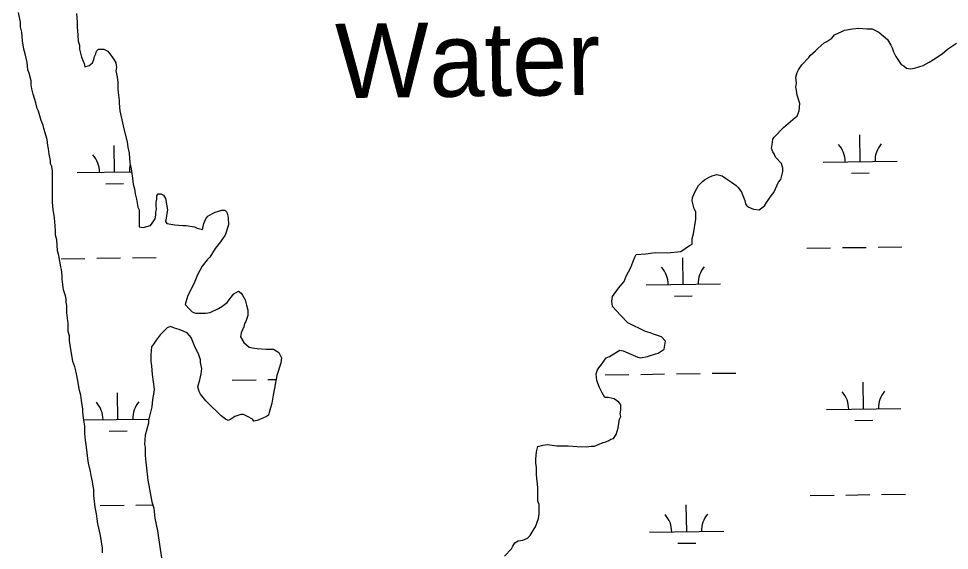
# Model space of a CAD drawing. Extents: x 3775218 to 3813389, y 343470 to 369318.
# Drawn here: x 3787496 to 3788749, y 357893 to 358608 of the extents above; entities that cross this region are included whole.
import ezdxf

# ---------------------------------------------------------------- set-up
doc = ezdxf.new("R2010")
doc.units = 0
for name, color, linetype in [('V-RIVR-IDEN', 7, 'Continuous'), ('V-TOPO-SHOR', 7, 'Continuous'), ('V-WETL-SWMP', 7, 'Continuous')]:
    doc.layers.add(name, color=color, linetype=linetype)

msp = doc.modelspace()

# ---------------------------------------------------------------- linework, layer by layer
at = {"layer": 'V-TOPO-SHOR'}
for points in [[(3787584.7, 358049.9), (3787584.7, 358059.9), (3787582.9, 358070.8), (3787582.1, 358079), (3787582.1, 358082.6), (3787580.3, 358094.4), (3787579.4, 358101.7), (3787577.6, 358108), (3787574.9, 358123.4), (3787573.2, 358132.5), (3787571.4, 358139.8), (3787568.7, 358147), (3787565.1, 358168.8), (3787564.2, 358175.2), (3787564.2, 358181.5), (3787562.4, 358187), (3787562.5, 358197.9), (3787560.7, 358212.4), (3787560.7, 358222.4), (3787559.8, 358226.9), (3787559.9, 358230.5), (3787559, 358235.1), (3787556.3, 358243.2), (3787554.5, 358257.7), (3787554.5, 358262.3), (3787553.6, 358270.4), (3787552.7, 358274.1), (3787550.1, 358289.5), (3787548.3, 358295.9), (3787547.4, 358310.4), (3787545.6, 358316.7), (3787545.6, 358322.2), (3787544.8, 358329.4), (3787543.9, 358340.3), (3787542.1, 358351.2), (3787541.2, 358361.2), (3787541.4, 358402.9), (3787540.5, 358409.3), (3787538.7, 358412.9), (3787538.7, 358417.4), (3787536.9, 358425.6), (3787536, 358432.9), (3787535.1, 358437.4), (3787534.2, 358445.6), (3787529.7, 358460.1), (3787528.9, 358464.6), (3787526.2, 358471), (3787522.6, 358483.7), (3787520.8, 358487.3), (3787519, 358494.6), (3787515.4, 358506.4), (3787513.6, 358513.6), (3787512.7, 358519.1), (3787512.7, 358524.5), (3787510, 358534.5), (3787508.2, 358539.1), (3787507.4, 358549), (3787504.7, 358560.8), (3787502.9, 358567.2), (3787501.1, 358578.1), (3787500.2, 358589.9), (3787498.4, 358597.1), (3787498.5, 358603.5), (3787495.8, 358616.2)], [(3787573.5, 358615), (3787574.4, 358603.2), (3787574.4, 358596.9), (3787575.3, 358586), (3787576.1, 358577.8), (3787577.9, 358572.4), (3787577.9, 358566.9), (3787580.6, 358556), (3787584.2, 358547.9), (3787585.1, 358543.3), (3787590.6, 358545.1), (3787595.1, 358548.7), (3787596.9, 358553.3), (3787597.8, 358556.9), (3787599.7, 358560.5), (3787600.6, 358564.1), (3787603.3, 358566.8), (3787610.6, 358566.8), (3787616, 358564.1), (3787622.3, 358555.9), (3787624.1, 358553.2), (3787626.8, 358548.6), (3787627.7, 358542.3), (3787626.8, 358537.7), (3787628.6, 358529.6), (3787629.5, 358522.3), (3787629.5, 358512.3), (3787631.2, 358497.8), (3787631.2, 358494.2), (3787632.1, 358484.2), (3787637.4, 358459.7), (3787641.9, 358442.5), (3787642.8, 358435.2), (3787644.6, 358427), (3787645.5, 358414.3), (3787647.3, 358406.2), (3787649, 358393.5)], [(3788352.5, 358293.3), (3788368.9, 358293.2), (3788387, 358295), (3788398.8, 358303.1), (3788402.5, 358304.9), (3788402.5, 358312.2), (3788404.3, 358318.5), (3788407.1, 358338.4), (3788407.1, 358348.4), (3788405.3, 358352.1), (3788402.6, 358362.9), (3788402.7, 358367.5), (3788406.3, 358375.6), (3788410.9, 358383.8), (3788416.3, 358389.2), (3788419.1, 358391), (3788425.4, 358394.6), (3788429.1, 358396.4), (3788435.4, 358398.2), (3788442.7, 358396.4), (3788447.2, 358393.6), (3788455.3, 358388.2), (3788461.7, 358383.6), (3788464.4, 358380.9), (3788468.9, 358374.5), (3788473.4, 358363.6), (3788474.3, 358359.1), (3788476.1, 358356.4), (3788478.8, 358354.5), (3788485.1, 358351.8), (3788492.4, 358350.9), (3788499.7, 358356.3), (3788502.4, 358360.8), (3788508.8, 358369.9), (3788512.4, 358374.4), (3788518.8, 358388), (3788521.6, 358391.6), (3788524.3, 358402.5), (3788524.3, 358407), (3788522.5, 358413.4), (3788514.4, 358421.5), (3788512.6, 358426.1), (3788510.8, 358428.8), (3788509, 358433.4), (3788509.9, 358438.8), (3788510.8, 358446), (3788512.7, 358448.8), (3788525.4, 358461.4), (3788540.9, 358475), (3788543.6, 358476.8), (3788546.3, 358484), (3788547.3, 358494), (3788543.7, 358504.9), (3788542.8, 358511.3), (3788541.9, 358515.8), (3788542.8, 358521.2), (3788541.9, 358529.4), (3788543.8, 358535.7), (3788545.6, 358539.4), (3788550.2, 358545.7), (3788559.3, 358555.6), (3788561.1, 358558.4), (3788568.4, 358564.7), (3788572, 358568.3), (3788580.2, 358575.5), (3788583.8, 358577.3), (3788590.2, 358581.8), (3788593.8, 358586.4), (3788603.8, 358590.9), (3788607.4, 358592.7), (3788618.3, 358594.5), (3788626.5, 358595.3), (3788637.4, 358594.4), (3788644.6, 358594.4), (3788653.7, 358589.8), (3788665.5, 358579.8), (3788670, 358572.5), (3788671.8, 358568.9), (3788673.6, 358563.4), (3788676.3, 358557.1), (3788683.5, 358546.2), (3788687.1, 358544.4), (3788690.7, 358541.6), (3788696.2, 358540.7), (3788701.6, 358541.6), (3788713.4, 358545.2), (3788721.6, 358549.7), (3788727, 358553.3), (3788738.9, 358560.5), (3788746.1, 358566.8), (3788758, 358575)], [(3787649, 358393.5), (3787649.9, 358385.3), (3787651.7, 358378.9), (3787652.6, 358372.6), (3787654.4, 358365.3), (3787656.2, 358354.4), (3787658, 358350.8), (3787657.9, 358328.1), (3787663.3, 358327.2), (3787673.3, 358329.9), (3787677.9, 358336.2), (3787679.7, 358338.9), (3787680.6, 358343.5), (3787680.6, 358348), (3787681.5, 358351.6), (3787680.7, 358356.2), (3787680.7, 358360.7), (3787681.6, 358365.2), (3787681.6, 358369.8), (3787683.4, 358372.5), (3787687.1, 358372.5), (3787690.7, 358370.6), (3787693.4, 358366.1), (3787696.1, 358350.7), (3787695.1, 358346.1), (3787694.2, 358339.8), (3787693.3, 358335.3), (3787695.1, 358332.5), (3787706, 358330.7), (3787716.9, 358329.8), (3787721.4, 358329.7), (3787732.3, 358327.9), (3787735.9, 358326.1), (3787743.1, 358324.2), (3787745, 358332.4), (3787747.7, 358338.7), (3787750.5, 358342.3), (3787756.8, 358345.9), (3787760.4, 358347.8), (3787769.5, 358350.4), (3787773.2, 358350.4), (3787775.9, 358347.7), (3787777.7, 358340.4), (3787778.5, 358330.5), (3787774, 358316.9), (3787771.2, 358313.3), (3787767.6, 358307.8), (3787760.3, 358298.8), (3787753, 358287), (3787749.4, 358283.4), (3787743, 358275.2), (3787736.6, 358263.5), (3787732.9, 358254.4), (3787722.9, 358234.5), (3787720.1, 358223.6), (3787725.6, 358217.3), (3787729.2, 358213.6), (3787733.7, 358211.8), (3787747.3, 358211.7), (3787753.7, 358212.6), (3787764.6, 358218), (3787769.1, 358220.7), (3787776.4, 358226.2), (3787781.9, 358233.4), (3787785.5, 358237.9), (3787791.9, 358241.5), (3787795.5, 358238.8), (3787797.3, 358236.1), (3787800.9, 358229.7), (3787802.7, 358222.5), (3787804.5, 358216.1), (3787804.4, 358208.8), (3787801.7, 358200.7), (3787799.9, 358198), (3787799, 358193.4), (3787795.3, 358185.3), (3787794.4, 358179.9), (3787798.9, 358172.6), (3787806.1, 358166.2), (3787810.7, 358165.3), (3787817, 358164.4), (3787828.8, 358163.4), (3787838.8, 358163.4), (3787846, 358158.8), (3787849.6, 358151.6), (3787848.7, 358145.2), (3787845, 358133.4), (3787843.2, 358128), (3787840.4, 358110.8), (3787838.6, 358101.7), (3787836.7, 358090.8), (3787833.1, 358078.1), (3787832.1, 358074.5), (3787829.4, 358072.7), (3787821.2, 358069.1), (3787816.7, 358067.3), (3787812.2, 358066.4), (3787810.4, 358069.1), (3787804, 358072.8), (3787798.6, 358075.5), (3787795, 358075.5)], [(3788149.9, 357884.9), (3788159, 357894.8), (3788160.8, 357898.4), (3788163.6, 357903), (3788168.1, 357905.7), (3788174.5, 357906.5), (3788180.8, 357909.2), (3788184.4, 357912.9), (3788189.9, 357921.9), (3788191.7, 357924.6), (3788195.4, 357935.5), (3788196.3, 357941.8), (3788196.4, 357954.5), (3788194.6, 357959.1), (3788194.6, 357977.2), (3788192.9, 357994.5), (3788192.9, 358004.4), (3788192, 358009.9), (3788192, 358015.3), (3788193, 358025.3), (3788194.8, 358032.6), (3788201.2, 358034.3), (3788207.5, 358035.2), (3788220.2, 358033.4), (3788235.6, 358033.3), (3788247.4, 358032.4), (3788260.1, 358032.3), (3788266.5, 358033.2), (3788271, 358033.2), (3788277.4, 358035.9), (3788282.8, 358037.7), (3788286.4, 358038.6), (3788290.1, 358040.4), (3788292.8, 358042.2), (3788296.4, 358043.1), (3788300.1, 358048.5), (3788302.8, 358057.6), (3788304.7, 358069.4), (3788306.5, 358073), (3788305.6, 358076.6), (3788306.5, 358081.2), (3788306.5, 358088.4), (3788303.8, 358092.1), (3788297.5, 358096.6), (3788289.3, 358098.5), (3788284.8, 358098.5), (3788281.2, 358104.8), (3788277.6, 358112.1), (3788274, 358121.2), (3788273.1, 358130.3), (3788274.9, 358135.7), (3788276.8, 358138.4), (3788280.4, 358142.9), (3788286.8, 358152), (3788291.3, 358153.8), (3788305, 358161.9), (3788309.5, 358161), (3788329.4, 358152.8), (3788333, 358151.8), (3788342.1, 358153.6), (3788353, 358157.2), (3788356.6, 358158.1), (3788364.8, 358163.5), (3788366.7, 358174.4), (3788361.3, 358179.9), (3788350.4, 358183.5), (3788345.9, 358185.4), (3788339.5, 358187.2), (3788316, 358199.1), (3788306, 358209.1), (3788295.2, 358220.9), (3788294.3, 358228.2), (3788295.2, 358234.5), (3788303.4, 358245.4), (3788310.7, 358254.4), (3788313.4, 358261.6), (3788319.8, 358273.4), (3788322.6, 358280.7), (3788325.3, 358287), (3788327.1, 358290.6), (3788339.8, 358291.5), (3788352.5, 358293.3)], [(3787795, 358075.5), (3787786.8, 358072.8), (3787781.3, 358069.2), (3787777.7, 358067.4), (3787774.1, 358069.3), (3787768.6, 358073.8), (3787764.1, 358078.4), (3787754.2, 358087.5), (3787747.8, 358093.8), (3787740.6, 358102.9), (3787738.8, 358106.6), (3787737, 358112.9), (3787739.8, 358122), (3787741.6, 358130.1), (3787742.5, 358137.4), (3787740.8, 358145.6), (3787740.8, 358149.2), (3787738.1, 358157.4), (3787733.6, 358165.5), (3787728.2, 358179.2), (3787722.7, 358185.5), (3787711.9, 358190.1), (3787705.5, 358191.9), (3787700.1, 358193.8), (3787695.6, 358192), (3787686.5, 358182.9), (3787681, 358175.7), (3787677.3, 358170.2), (3787674.6, 358166.6), (3787673.7, 358155.7), (3787673.6, 358146.7), (3787674.5, 358141.2), (3787675.4, 358129.4), (3787678.1, 358109.5), (3787678, 358105.8), (3787676.2, 358095.9), (3787675.3, 358085.9), (3787670.7, 358067.8), (3787670.7, 358064.1), (3787666.1, 358047.8), (3787665.1, 358035.1), (3787666, 358031.5), (3787666, 358020.6), (3787666.9, 358011.6), (3787669.5, 357987.1), (3787674.9, 357958), (3787677.6, 357949.8), (3787679.3, 357936.2), (3787682.9, 357919), (3787686.4, 357894.5), (3787690, 357871.8)], [(3787608.7, 357889.3), (3787608.7, 357895.7), (3787606, 357912.9), (3787602.4, 357928.4), (3787600.7, 357942), (3787598.9, 357951), (3787597.1, 357966.5), (3787597.1, 357974.6), (3787596.2, 357979.2), (3787595.4, 357985.5), (3787593.6, 357993.7), (3787592.7, 357999.1), (3787590, 358010), (3787589.1, 358016.4), (3787587.3, 358031.8), (3787585.6, 358040.9), (3787584.7, 358049.9)]]:
    msp.add_lwpolyline(points, dxfattribs=at)
at = {"layer": 'V-WETL-SWMP'}
for p, q in [((3788628.5, 358415.8), (3788627.9, 358451.7)), ((3787624.7, 358401.6), (3787624.2, 358437.6)), ((3788578.5, 358415), (3788678.5, 358416.5)), ((3787574.7, 358400.9), (3787647.8, 358401.9)), ((3788616.7, 358400.2), (3788640.7, 358400.5)), ((3787613, 358386), (3787637, 358386.3)), ((3788556.7, 358299.3), (3788588.7, 358299.7)), ((3788604.7, 358300), (3788636.7, 358300.4)), ((3788652.7, 358300.6), (3788684.7, 358301.1)), ((3787553, 358285.1), (3787585, 358285.6)), ((3787601, 358285.8), (3787633, 358286.3)), ((3787649, 358286.5), (3787681, 358286.9)), ((3788390.3, 358250.5), (3788389.8, 358286.5)), ((3788340.3, 358249.8), (3788440.3, 358251.2)), ((3788378.5, 358234.9), (3788402.5, 358235.3)), ((3787783.3, 358121.9), (3787815.3, 358122.3)), ((3787831.3, 358122.5), (3787842.3, 358122.7)), ((3788285.2, 358128.9), (3788317.2, 358129.4)), ((3788333.1, 358129.6), (3788365.1, 358130.1)), ((3788381.1, 358130.3), (3788413.1, 358130.8)), ((3788429.1, 358131), (3788461.1, 358131.4)), ((3788633.2, 358083.1), (3788632.6, 358119.1)), ((3787629.4, 358068.9), (3787628.9, 358104.9)), ((3788583.2, 358082.4), (3788683.1, 358083.8)), ((3787583.3, 358068.3), (3787671.1, 358069.5)), ((3788621.4, 358067.5), (3788645.4, 358067.8)), ((3787617.7, 358053.3), (3787641.7, 358053.7)), ((3788561.4, 357966.7), (3788593.4, 357967.1)), ((3788609.4, 357967.3), (3788641.4, 357967.8)), ((3788657.4, 357968), (3788689.4, 357968.5)), ((3787605.7, 357953.2), (3787637.7, 357953.6)), ((3787653.7, 357953.8), (3787676.1, 357954.2)), ((3788395, 357917.9), (3788394.5, 357953.9)), ((3788345, 357917.2), (3788445, 357918.6)), ((3788383.2, 357902.3), (3788407.2, 357902.6))]:
    msp.add_line(p, q, dxfattribs=at)
for points in [[(3787584.7, 358049.9), (3787584.7, 358059.9), (3787582.9, 358070.8), (3787582.1, 358079), (3787582.1, 358082.6), (3787580.3, 358094.4), (3787579.4, 358101.7), (3787577.6, 358108), (3787574.9, 358123.4), (3787573.2, 358132.5), (3787571.4, 358139.8), (3787568.7, 358147), (3787565.1, 358168.8), (3787564.2, 358175.2), (3787564.2, 358181.5), (3787562.4, 358187), (3787562.5, 358197.9), (3787560.7, 358212.4), (3787560.7, 358222.4), (3787559.8, 358226.9), (3787559.9, 358230.5), (3787559, 358235.1), (3787556.3, 358243.2), (3787554.5, 358257.7), (3787554.5, 358262.3), (3787553.6, 358270.4), (3787552.7, 358274.1), (3787550.1, 358289.5), (3787548.3, 358295.9), (3787547.4, 358310.4), (3787545.6, 358316.7), (3787545.6, 358322.2), (3787544.8, 358329.4), (3787543.9, 358340.3), (3787542.1, 358351.2), (3787541.2, 358361.2), (3787541.4, 358402.9), (3787540.5, 358409.3), (3787538.7, 358412.9), (3787538.7, 358417.4), (3787536.9, 358425.6), (3787536, 358432.9), (3787535.1, 358437.4), (3787534.2, 358445.6), (3787529.7, 358460.1), (3787528.9, 358464.6), (3787526.2, 358471), (3787522.6, 358483.7), (3787520.8, 358487.3), (3787519, 358494.6), (3787515.4, 358506.4), (3787513.6, 358513.6), (3787512.7, 358519.1), (3787512.7, 358524.5), (3787510, 358534.5), (3787508.2, 358539.1), (3787507.4, 358549), (3787504.7, 358560.8), (3787502.9, 358567.2), (3787501.1, 358578.1), (3787500.2, 358589.9), (3787498.4, 358597.1), (3787498.5, 358603.5), (3787495.8, 358616.2)], [(3787573.5, 358615), (3787574.4, 358603.2), (3787574.4, 358596.9), (3787575.3, 358586), (3787576.1, 358577.8), (3787577.9, 358572.4), (3787577.9, 358566.9), (3787580.6, 358556), (3787584.2, 358547.9), (3787585.1, 358543.3), (3787590.6, 358545.1), (3787595.1, 358548.7), (3787596.9, 358553.3), (3787597.8, 358556.9), (3787599.7, 358560.5), (3787600.6, 358564.1), (3787603.3, 358566.8), (3787610.6, 358566.8), (3787616, 358564.1), (3787622.3, 358555.9), (3787624.1, 358553.2), (3787626.8, 358548.6), (3787627.7, 358542.3), (3787626.8, 358537.7), (3787628.6, 358529.6), (3787629.5, 358522.3), (3787629.5, 358512.3), (3787631.2, 358497.8), (3787631.2, 358494.2), (3787632.1, 358484.2), (3787637.4, 358459.7), (3787641.9, 358442.5), (3787642.8, 358435.2), (3787644.6, 358427), (3787645.5, 358414.3), (3787647.3, 358406.2), (3787649, 358393.5)], [(3788352.5, 358293.3), (3788368.9, 358293.2), (3788387, 358295), (3788398.8, 358303.1), (3788402.5, 358304.9), (3788402.5, 358312.2), (3788404.3, 358318.5), (3788407.1, 358338.4), (3788407.1, 358348.4), (3788405.3, 358352.1), (3788402.6, 358362.9), (3788402.7, 358367.5), (3788406.3, 358375.6), (3788410.9, 358383.8), (3788416.3, 358389.2), (3788419.1, 358391), (3788425.4, 358394.6), (3788429.1, 358396.4), (3788435.4, 358398.2), (3788442.7, 358396.4), (3788447.2, 358393.6), (3788455.3, 358388.2), (3788461.7, 358383.6), (3788464.4, 358380.9), (3788468.9, 358374.5), (3788473.4, 358363.6), (3788474.3, 358359.1), (3788476.1, 358356.4), (3788478.8, 358354.5), (3788485.1, 358351.8), (3788492.4, 358350.9), (3788499.7, 358356.3), (3788502.4, 358360.8), (3788508.8, 358369.9), (3788512.4, 358374.4), (3788518.8, 358388), (3788521.6, 358391.6), (3788524.3, 358402.5), (3788524.3, 358407), (3788522.5, 358413.4), (3788514.4, 358421.5), (3788512.6, 358426.1), (3788510.8, 358428.8), (3788509, 358433.4), (3788509.9, 358438.8), (3788510.8, 358446), (3788512.7, 358448.8), (3788525.4, 358461.4), (3788540.9, 358475), (3788543.6, 358476.8), (3788546.3, 358484), (3788547.3, 358494), (3788543.7, 358504.9), (3788542.8, 358511.3), (3788541.9, 358515.8), (3788542.8, 358521.2), (3788541.9, 358529.4), (3788543.8, 358535.7), (3788545.6, 358539.4), (3788550.2, 358545.7), (3788559.3, 358555.6), (3788561.1, 358558.4), (3788568.4, 358564.7), (3788572, 358568.3), (3788580.2, 358575.5), (3788583.8, 358577.3), (3788590.2, 358581.8), (3788593.8, 358586.4), (3788603.8, 358590.9), (3788607.4, 358592.7), (3788618.3, 358594.5), (3788626.5, 358595.3), (3788637.4, 358594.4), (3788644.6, 358594.4), (3788653.7, 358589.8), (3788665.5, 358579.8), (3788670, 358572.5), (3788671.8, 358568.9), (3788673.6, 358563.4), (3788676.3, 358557.1), (3788683.5, 358546.2), (3788687.1, 358544.4), (3788690.7, 358541.6), (3788696.2, 358540.7), (3788701.6, 358541.6), (3788713.4, 358545.2), (3788721.6, 358549.7), (3788727, 358553.3), (3788738.9, 358560.5), (3788746.1, 358566.8), (3788758, 358575)], [(3787649, 358393.5), (3787649.9, 358385.3), (3787651.7, 358378.9), (3787652.6, 358372.6), (3787654.4, 358365.3), (3787656.2, 358354.4), (3787658, 358350.8), (3787657.9, 358328.1), (3787663.3, 358327.2), (3787673.3, 358329.9), (3787677.9, 358336.2), (3787679.7, 358338.9), (3787680.6, 358343.5), (3787680.6, 358348), (3787681.5, 358351.6), (3787680.7, 358356.2), (3787680.7, 358360.7), (3787681.6, 358365.2), (3787681.6, 358369.8), (3787683.4, 358372.5), (3787687.1, 358372.5), (3787690.7, 358370.6), (3787693.4, 358366.1), (3787696.1, 358350.7), (3787695.1, 358346.1), (3787694.2, 358339.8), (3787693.3, 358335.3), (3787695.1, 358332.5), (3787706, 358330.7), (3787716.9, 358329.8), (3787721.4, 358329.7), (3787732.3, 358327.9), (3787735.9, 358326.1), (3787743.1, 358324.2), (3787745, 358332.4), (3787747.7, 358338.7), (3787750.5, 358342.3), (3787756.8, 358345.9), (3787760.4, 358347.8), (3787769.5, 358350.4), (3787773.2, 358350.4), (3787775.9, 358347.7), (3787777.7, 358340.4), (3787778.5, 358330.5), (3787774, 358316.9), (3787771.2, 358313.3), (3787767.6, 358307.8), (3787760.3, 358298.8), (3787753, 358287), (3787749.4, 358283.4), (3787743, 358275.2), (3787736.6, 358263.5), (3787732.9, 358254.4), (3787722.9, 358234.5), (3787720.1, 358223.6), (3787725.6, 358217.3), (3787729.2, 358213.6), (3787733.7, 358211.8), (3787747.3, 358211.7), (3787753.7, 358212.6), (3787764.6, 358218), (3787769.1, 358220.7), (3787776.4, 358226.2), (3787781.9, 358233.4), (3787785.5, 358237.9), (3787791.9, 358241.5), (3787795.5, 358238.8), (3787797.3, 358236.1), (3787800.9, 358229.7), (3787802.7, 358222.5), (3787804.5, 358216.1), (3787804.4, 358208.8), (3787801.7, 358200.7), (3787799.9, 358198), (3787799, 358193.4), (3787795.3, 358185.3), (3787794.4, 358179.9), (3787798.9, 358172.6), (3787806.1, 358166.2), (3787810.7, 358165.3), (3787817, 358164.4), (3787828.8, 358163.4), (3787838.8, 358163.4), (3787846, 358158.8), (3787849.6, 358151.6), (3787848.7, 358145.2), (3787845, 358133.4), (3787843.2, 358128), (3787840.4, 358110.8), (3787838.6, 358101.7), (3787836.7, 358090.8), (3787833.1, 358078.1), (3787832.1, 358074.5), (3787829.4, 358072.7), (3787821.2, 358069.1), (3787816.7, 358067.3), (3787812.2, 358066.4), (3787810.4, 358069.1), (3787804, 358072.8), (3787798.6, 358075.5), (3787795, 358075.5)], [(3788149.9, 357884.9), (3788159, 357894.8), (3788160.8, 357898.4), (3788163.6, 357903), (3788168.1, 357905.7), (3788174.5, 357906.5), (3788180.8, 357909.2), (3788184.4, 357912.9), (3788189.9, 357921.9), (3788191.7, 357924.6), (3788195.4, 357935.5), (3788196.3, 357941.8), (3788196.4, 357954.5), (3788194.6, 357959.1), (3788194.6, 357977.2), (3788192.9, 357994.5), (3788192.9, 358004.4), (3788192, 358009.9), (3788192, 358015.3), (3788193, 358025.3), (3788194.8, 358032.6), (3788201.2, 358034.3), (3788207.5, 358035.2), (3788220.2, 358033.4), (3788235.6, 358033.3), (3788247.4, 358032.4), (3788260.1, 358032.3), (3788266.5, 358033.2), (3788271, 358033.2), (3788277.4, 358035.9), (3788282.8, 358037.7), (3788286.4, 358038.6), (3788290.1, 358040.4), (3788292.8, 358042.2), (3788296.4, 358043.1), (3788300.1, 358048.5), (3788302.8, 358057.6), (3788304.7, 358069.4), (3788306.5, 358073), (3788305.6, 358076.6), (3788306.5, 358081.2), (3788306.5, 358088.4), (3788303.8, 358092.1), (3788297.5, 358096.6), (3788289.3, 358098.5), (3788284.8, 358098.5), (3788281.2, 358104.8), (3788277.6, 358112.1), (3788274, 358121.2), (3788273.1, 358130.3), (3788274.9, 358135.7), (3788276.8, 358138.4), (3788280.4, 358142.9), (3788286.8, 358152), (3788291.3, 358153.8), (3788305, 358161.9), (3788309.5, 358161), (3788329.4, 358152.8), (3788333, 358151.8), (3788342.1, 358153.6), (3788353, 358157.2), (3788356.6, 358158.1), (3788364.8, 358163.5), (3788366.7, 358174.4), (3788361.3, 358179.9), (3788350.4, 358183.5), (3788345.9, 358185.4), (3788339.5, 358187.2), (3788316, 358199.1), (3788306, 358209.1), (3788295.2, 358220.9), (3788294.3, 358228.2), (3788295.2, 358234.5), (3788303.4, 358245.4), (3788310.7, 358254.4), (3788313.4, 358261.6), (3788319.8, 358273.4), (3788322.6, 358280.7), (3788325.3, 358287), (3788327.1, 358290.6), (3788339.8, 358291.5), (3788352.5, 358293.3)], [(3787795, 358075.5), (3787786.8, 358072.8), (3787781.3, 358069.2), (3787777.7, 358067.4), (3787774.1, 358069.3), (3787768.6, 358073.8), (3787764.1, 358078.4), (3787754.2, 358087.5), (3787747.8, 358093.8), (3787740.6, 358102.9), (3787738.8, 358106.6), (3787737, 358112.9), (3787739.8, 358122), (3787741.6, 358130.1), (3787742.5, 358137.4), (3787740.8, 358145.6), (3787740.8, 358149.2), (3787738.1, 358157.4), (3787733.6, 358165.5), (3787728.2, 358179.2), (3787722.7, 358185.5), (3787711.9, 358190.1), (3787705.5, 358191.9), (3787700.1, 358193.8), (3787695.6, 358192), (3787686.5, 358182.9), (3787681, 358175.7), (3787677.3, 358170.2), (3787674.6, 358166.6), (3787673.7, 358155.7), (3787673.6, 358146.7), (3787674.5, 358141.2), (3787675.4, 358129.4), (3787678.1, 358109.5), (3787678, 358105.8), (3787676.2, 358095.9), (3787675.3, 358085.9), (3787670.7, 358067.8), (3787670.7, 358064.1), (3787666.1, 358047.8), (3787665.1, 358035.1), (3787666, 358031.5), (3787666, 358020.6), (3787666.9, 358011.6), (3787669.5, 357987.1), (3787674.9, 357958), (3787677.6, 357949.8), (3787679.3, 357936.2), (3787682.9, 357919), (3787686.4, 357894.5), (3787690, 357871.8)], [(3787608.7, 357889.3), (3787608.7, 357895.7), (3787606, 357912.9), (3787602.4, 357928.4), (3787600.7, 357942), (3787598.9, 357951), (3787597.1, 357966.5), (3787597.1, 357974.6), (3787596.2, 357979.2), (3787595.4, 357985.5), (3787593.6, 357993.7), (3787592.7, 357999.1), (3787590, 358010), (3787589.1, 358016.4), (3787587.3, 358031.8), (3787585.6, 358040.9), (3787584.7, 358049.9)]]:
    msp.add_lwpolyline(points, dxfattribs=at)
for centre, start, end in [((3788573.2, 358415.4), 0.0365, 41.5802), ((3788683.7, 358417), 140.0365, 181.5802), ((3787569.5, 358401.3), 0.0365, 41.5802), ((3787680, 358402.8), 164.8032, 181.5802), ((3788335, 358250.2), 0.0365, 41.5802), ((3788445.5, 358251.8), 140.0365, 181.5802), ((3788577.9, 358082.8), 0.0365, 41.5802), ((3788688.4, 358084.4), 140.0365, 181.5802), ((3787574.2, 358068.6), 0.0365, 41.5802), ((3787684.7, 358070.2), 140.0365, 181.5802), ((3788339.7, 357917.6), 0.0365, 41.5802), ((3788450.2, 357919.1), 140.0365, 181.5802)]:
    msp.add_arc(centre, 35.2, start, end, dxfattribs=at)

# ---------------------------------------------------------------- texts
at = {"layer": 'V-RIVR-IDEN'}
msp.add_text('Water', height=100, rotation=0.7588, dxfattribs=at).set_placement((3787922.7, 358501))

doc.saveas('drawing.dxf')
